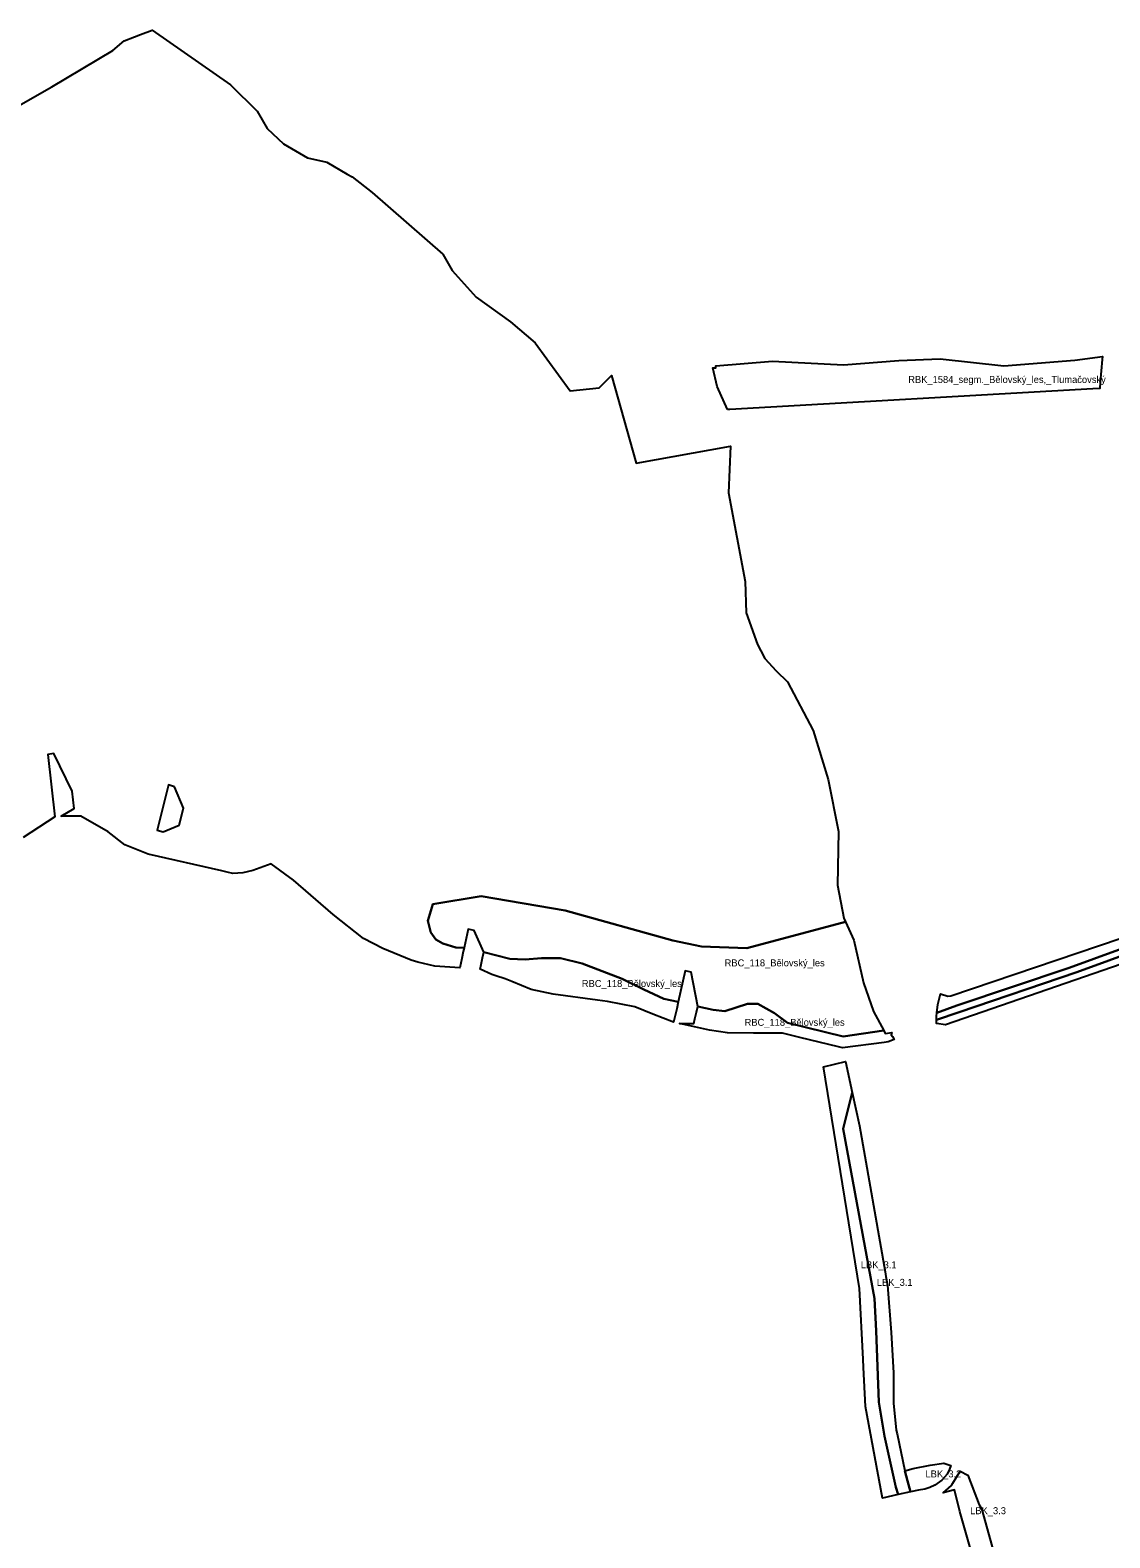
# Model space of a CAD drawing. Extents: x -535894 to -532763, y -1165802 to -1163647.
# Drawn here: x -534659 to -533885, y -1164727 to -1163647 of the extents above; entities that cross this region are included whole.
import ezdxf

# ---------------------------------------------------------------- set-up
doc = ezdxf.new("R2010")
doc.units = 0
for name, color, linetype in [('91250013', 7, 'Continuous'), ('91250023', 7, 'Continuous'), ('91260023', 7, 'Continuous'), ('91280013', 7, 'Continuous'), ('91280023', 7, 'Continuous')]:
    doc.layers.add(name, color=color, linetype=linetype)

msp = doc.modelspace()

# ---------------------------------------------------------------- linework, layer by layer
at = {"layer": '91250013'}
msp.add_lwpolyline([(-534718.97, -1163730.71), (-534642.84, -1163687.62), (-534599.15, -1163661.49), (-534591.03, -1163654.51), (-534583.72, -1163651.75), (-534579.5, -1163650.15), (-534570.98, -1163646.93), (-534514.86, -1163686.14), (-534495.67, -1163705.05), (-534488.62, -1163717.48), (-534476.78, -1163728.4), (-534459.7, -1163738.33), (-534445.87, -1163741.61), (-534431.31, -1163750.05), (-534427.72, -1163752.13), (-534413.24, -1163763.36), (-534362.72, -1163807.37), (-534355.93, -1163819.24), (-534338.84, -1163838.27), (-534314.16, -1163855.97), (-534296.47, -1163870.97), (-534271.49, -1163905.38), (-534250.57, -1163903.14), (-534241.76, -1163894.34), (-534224.22, -1163957.18), (-534156.41, -1163945.04), (-534157.94, -1163978.43), (-534146.05, -1164041.92), (-534145.18, -1164064.32), (-534137.15, -1164087.2), (-534134.69, -1164091.75), (-534131.77, -1164097.12), (-534123.86, -1164105.89), (-534115.56, -1164113.93), (-534097.11, -1164148.68), (-534086.47, -1164183.86), (-534079.09, -1164221.21), (-534079.7, -1164259.55), (-534075.33, -1164283.15), (-534074.04, -1164285.93), (-534144.82, -1164304.74), (-534177.29, -1164303.6), (-534197.87, -1164299.21), (-534274.99, -1164277.69), (-534335.13, -1164267.45), (-534369.81, -1164273.2), (-534373.54, -1164285.18), (-534371.26, -1164293.52), (-534367.73, -1164298.58), (-534362.68, -1164301.36), (-534353.37, -1164304.203), (-534347.47, -1164304.55), (-534347.994, -1164306.993), (-534349.078, -1164312.05), (-534350.52, -1164318.78), (-534368.42, -1164317.5), (-534380.51, -1164314.71), (-534385.3, -1164313.34), (-534405.79, -1164304.82), (-534419.47, -1164297.82), (-534441.39, -1164280.53), (-534469.68, -1164256.06), (-534485.85, -1164244.28), (-534498.96, -1164248.96), (-534506.03, -1164250.83), (-534513.1, -1164251.12), (-534517.155, -1164250.247), (-534521.14, -1164249.39), (-534573.95, -1164237.35), (-534590.55, -1164230.7), (-534602.67, -1164221.46), (-534622.278, -1164210.134), (-534636.34, -1164210.08), (-534626.89, -1164204.68), (-534628.3, -1164192.26), (-534641.46, -1164165.28), (-534645.78, -1164165.89), (-534640.71, -1164210.58), (-534663.54, -1164225.41)], dxfattribs=at)
for points in [[(-534555.08, -1164189.08), (-534559.25, -1164187.61), (-534567.49, -1164220.26), (-534563.23, -1164221.34), (-534551.69, -1164216.52), (-534548.63, -1164204.4)], [(-534225.01, -1164346.8), (-534244.58, -1164342.94), (-534251.765, -1164341.955), (-534283.55, -1164337.6), (-534299.28, -1164334.42), (-534313.141, -1164328.664), (-534318.04, -1164326.63), (-534324.797, -1164324.417), (-534327.542, -1164323.518), (-534335.99, -1164319.7), (-534335.291, -1164316.439), (-534334.234, -1164311.511), (-534333.37, -1164307.48), (-534314.69, -1164312.22), (-534303.58, -1164312.73), (-534291.96, -1164311.97), (-534278.32, -1164311.97), (-534262.91, -1164315.76), (-534234.12, -1164326.63), (-534218.68, -1164334.39), (-534204.157, -1164340.904), (-534193.926, -1164343.087), (-534195.06, -1164348.062), (-534196.171, -1164352.932), (-534197.24, -1164357.62), (-534212.04, -1164352.1)], [(-534168.89, -1164348.83), (-534160.642, -1164349.807), (-534144.37, -1164344.48), (-534136.93, -1164344.68), (-534124.97, -1164351.29), (-534115.69, -1164358.28), (-534075.84, -1164368.05), (-534046.67, -1164363.75), (-534045.73, -1164365.82), (-534040.96, -1164365.04), (-534041.28, -1164366.81), (-534040.3, -1164367.94), (-534039.205, -1164370.137), (-534043.41, -1164371.85), (-534046.42, -1164372.25), (-534076.23, -1164376.18), (-534079.11, -1164375.48), (-534106.79, -1164368.71), (-534119.2, -1164365.67), (-534136.822, -1164365.594), (-534139.96, -1164365.58), (-534158.72, -1164365.3), (-534171.42, -1164363.56), (-534192.95, -1164358.6), (-534182.72, -1164358.73), (-534181.972, -1164355.438), (-534180.864, -1164350.562), (-534179.95, -1164346.54)]]:
    msp.add_lwpolyline(points, close=True, dxfattribs=at)
at = {"layer": '91250023'}
msp.add_lwpolyline([(-534144.37, -1164344.48), (-534160.642, -1164349.807), (-534168.89, -1164348.83), (-534179.95, -1164346.54), (-534184.57, -1164321.84), (-534188.86, -1164320.87), (-534193.926, -1164343.087), (-534204.157, -1164340.904), (-534218.68, -1164334.39), (-534234.12, -1164326.63), (-534262.91, -1164315.76), (-534278.32, -1164311.97), (-534291.96, -1164311.97), (-534303.58, -1164312.73), (-534314.69, -1164312.22), (-534333.37, -1164307.48), (-534340.29, -1164292.04), (-534344.59, -1164291.11), (-534347.47, -1164304.55), (-534353.37, -1164304.203), (-534362.68, -1164301.36), (-534367.73, -1164298.58), (-534371.26, -1164293.52), (-534373.54, -1164285.18), (-534369.81, -1164273.2), (-534335.13, -1164267.45), (-534274.99, -1164277.69), (-534197.87, -1164299.21), (-534177.29, -1164303.6), (-534144.82, -1164304.74), (-534074.04, -1164285.93), (-534068.03, -1164298.87), (-534061.1, -1164329.42), (-534054.06, -1164350.04), (-534046.67, -1164363.75), (-534075.84, -1164368.05), (-534115.69, -1164358.28), (-534124.97, -1164351.29), (-534136.93, -1164344.68)], close=True, dxfattribs=at)
at = {"layer": '91260023'}
msp.add_lwpolyline([(-534158.612, -1163918.789), (-534166.07, -1163902.27), (-534169.16, -1163888.95), (-534166.94, -1163888.88), (-534167.05, -1163887.54), (-534126.29, -1163884.14), (-534075.55, -1163886.63), (-534035.93, -1163883.59), (-534006.23, -1163882.44), (-533960.63, -1163887.47), (-533909.61, -1163883.3), (-533889.94, -1163880.68), (-533890.12, -1163882.84), (-533891.45, -1163899.11), (-533891.816, -1163903.599), (-533896.856, -1163903.885), (-534157.028, -1163918.699)], close=True, dxfattribs=at)
at = {"layer": '91280013'}
for points in [[(-534008.513, -1164350.985), (-533994.159, -1164345.79), (-533913.758, -1164318.806), (-533878.291, -1164305.987), (-533720.886, -1164249.096), (-533718.598, -1164247.919), (-533716.005, -1164251.393), (-533719.497, -1164253.06), (-533908.348, -1164321.995), (-533992.489, -1164350.51), (-534008.777, -1164356.096), (-534008.751, -1164353.346)], [(-534069.206, -1164408.204), (-534064.01, -1164431.89), (-534045.697, -1164536.686), (-534045.118, -1164539.999), (-534044.05, -1164546.11), (-534041.27, -1164579.97), (-534039.76, -1164609.03), (-534039.76, -1164630.76), (-534037.74, -1164649.96), (-534037.13, -1164652.786), (-534031.42, -1164679.27), (-534029.566, -1164686.448), (-534027.567, -1164694.184), (-534036.347, -1164696.241), (-534037.87, -1164691), (-534046.04, -1164654.24), (-534050.05, -1164630.03), (-534052.06, -1164578.82), (-534053.31, -1164555.72), (-534075.643, -1164434.195)]]:
    msp.add_lwpolyline(points, close=True, dxfattribs=at)
at = {"layer": '91280023'}
for points in [[(-533720.886, -1164249.096), (-533878.291, -1164305.987), (-533913.758, -1164318.806), (-533994.159, -1164345.79), (-534008.513, -1164350.985), (-534007.911, -1164344.987), (-534005.963, -1164337.46), (-534000.781, -1164338.991), (-533998.54, -1164338.94), (-533877.27, -1164297.75), (-533723.64, -1164241.09), (-533718.598, -1164247.919)], [(-533716.005, -1164251.393), (-533710.415, -1164258.881), (-534002.49, -1164359.73), (-534008.797, -1164358.709), (-534008.777, -1164356.096), (-533992.489, -1164350.51), (-533908.348, -1164321.995), (-533719.497, -1164253.06)], [(-534052.06, -1164578.82), (-534050.05, -1164630.03), (-534046.04, -1164654.24), (-534037.87, -1164691), (-534036.347, -1164696.241), (-534047.573, -1164698.892), (-534059.702, -1164633.021), (-534061.096, -1164605.058), (-534061.383, -1164599.296), (-534063.908, -1164548.655), (-534089.79, -1164389.609), (-534074.121, -1164385.794), (-534069.206, -1164408.204), (-534075.643, -1164434.195), (-534053.31, -1164555.72)], [(-534027.567, -1164694.184), (-534029.566, -1164686.448), (-534031.42, -1164679.27), (-534025.511, -1164677.617), (-534013.382, -1164675.046), (-534003.577, -1164673.621), (-533998.47, -1164675.42), (-533999.598, -1164677.998), (-534001.2, -1164681.66), (-534004.94, -1164685.91), (-534010.017, -1164689.514), (-534013.67, -1164691.24), (-534017.22, -1164692.32), (-534021.634, -1164693.103)], [(-533992.01, -1164708.4), (-533996.002, -1164692.697), (-534004.077, -1164694.939), (-533998.16, -1164689.6), (-533997.187, -1164688.034), (-533991.85, -1164679.44), (-533986.32, -1164682.27), (-533978.18, -1164703.55), (-533976.638, -1164706.229), (-533965.282, -1164746.513), (-533980.66, -1164747.97), (-533983.41, -1164738.37)]]:
    msp.add_lwpolyline(points, close=True, dxfattribs=at)

# ---------------------------------------------------------------- texts
at = {"layer": '91250013'}
for p in [(-534263.0621, -1164332.55), (-534146.3845, -1164360.33)]:
    msp.add_text('RBC_118_Bělovský_les', height=5, rotation=0, dxfattribs=at).set_placement(p)
at = {"layer": '91250023'}
msp.add_text('RBC_118_Bělovský_les', height=5, rotation=0.0000001, dxfattribs=at).set_placement((-534160.6933, -1164317.75))
at = {"layer": '91260023'}
msp.add_text('RBK_1584_segm._Bělovský_les,_Tlumačovský', height=5, rotation=360, dxfattribs=at).set_placement((-534029.0796, -1163899.7345))
at = {"layer": '91280013'}
msp.add_text('LBK_3.1', height=5, rotation=360, dxfattribs=at).set_placement((-534051.605, -1164546.6449))
at = {"layer": '91280023'}
for s, rotation, p in [('LBK_3.1', 359.9999999, (-534063.0685, -1164534.0555)), ('LBK_3.2', 0, (-534016.6984, -1164683.9025)), ('LBK_3.3', 0, (-533984.6795, -1164710.2523))]:
    msp.add_text(s, height=5, rotation=rotation, dxfattribs=at).set_placement(p)

doc.saveas('drawing.dxf')
